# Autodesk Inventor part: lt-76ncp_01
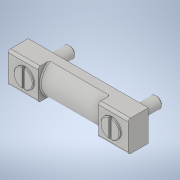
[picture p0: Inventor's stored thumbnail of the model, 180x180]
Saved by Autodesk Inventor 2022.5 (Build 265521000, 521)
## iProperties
Created: 2021-11
Part Number: lt-76ncp_01
Material: 一般
Document SubType Name: Modeling
Designer: ImaoCorp
Density: 1 g/cm^3
Appearance: 既定
Author: ImaoCorp
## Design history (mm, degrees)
feature "lt-76ncp_01"
node "ソリッド1"
